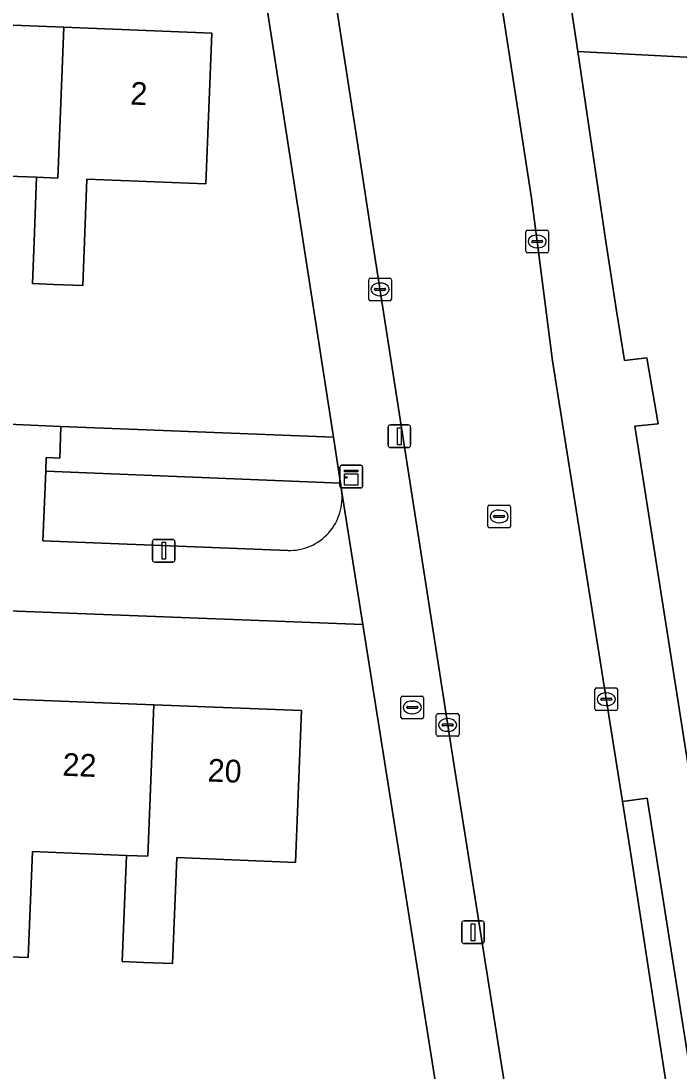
# Model space of a CAD drawing. Extents: x 160077 to 160948, y 386481 to 387498.
# Drawn here: x 160783.5 to 160812.49, y 386713.48 to 386759.71 of the extents above; entities that cross this region are included whole.
import ezdxf

# ---------------------------------------------------------------- set-up
doc = ezdxf.new("R2010")
doc.units = 0
for name, color, linetype in [('IMGEO_Brandkraan', 7, 'Continuous'), ('IMGEO_Erf', 7, 'Continuous'), ('IMGEO_Groenvoorziening', 7, 'Continuous'), ('IMGEO_Kast', 7, 'Continuous'), ('IMGEO_Kolk', 7, 'Continuous'), ('IMGEO_Lichtmast', 7, 'Continuous'), ('IMGEO_Pand', 7, 'Continuous'), ('IMGEO_Pand_nummerreeks', 7, 'Continuous'), ('IMGEO_Rijbaan_lokaal_open', 7, 'Continuous'), ('IMGEO_Rioolput', 7, 'Continuous'), ('IMGEO_Voetpad_open', 7, 'Continuous')]:
    doc.layers.add(name, color=color, linetype=linetype)

msp = doc.modelspace()

# ---------------------------------------------------------------- linework, layer by layer
at = {"layer": 'IMGEO_Brandkraan'}
for p, q in [((160800.311, 386729.989), (160801.163, 386729.989)), ((160800.236, 386729.063), (160800.236, 386729.915)), ((160800.495, 386729.483), (160800.495, 386729.495)), ((160800.538, 386729.532), (160800.936, 386729.532)), ((160800.724, 386729.769), (160800.749, 386729.769)), ((160800.979, 386729.495), (160800.979, 386729.483)), ((160801.237, 386729.915), (160801.237, 386729.063)), ((160800.933, 386729.446), (160800.535, 386729.446)), ((160800.747, 386729.209), (160800.722, 386729.209)), ((160801.163, 386728.989), (160800.311, 386728.989))]:
    msp.add_line(p, q, dxfattribs=at)
for points in [[(160800.311, 386729.989), (160801.163, 386729.989)], [(160800.236, 386729.063), (160800.236, 386729.915)], [(160801.237, 386729.915), (160801.237, 386729.063)], [(160801.163, 386728.989), (160800.311, 386728.989)]]:
    msp.add_lwpolyline(points, dxfattribs=at)
for centre, radius, start, end in [((160800.313, 386729.913), 0.0765, 91.552, 178.448), ((160800.313, 386729.913), 0.0765, 91.552, 178.448), ((160801.161, 386729.913), 0.0765, 1.552, 88.448), ((160801.161, 386729.913), 0.0765, 1.552, 88.448), ((160800.535, 386729.492), 0.0403, 85.8775, 175.7526), ((160800.532, 386729.482), 0.0366, 178.938, 274.7102), ((160800.936, 386729.489), 0.043, 264.8664, 352.4533), ((160800.94, 386729.494), 0.0386, 1.7309, 96.639), ((160800.313, 386729.065), 0.0765, 181.552, 268.448), ((160800.313, 386729.065), 0.0765, 181.552, 268.448), ((160801.161, 386729.065), 0.0765, 271.552, 358.448), ((160801.161, 386729.065), 0.0765, 271.552, 358.448)]:
    msp.add_arc(centre, radius, start, end, dxfattribs=at)
for centre, major_axis, ratio, start_param, end_param in [((160800.723, 386729.489), (-0.387, 0.002), 0.722429, 4.712389, 7.853982), ((160800.748, 386729.489), (-0.39, 0.002), 0.717154, 1.570796, 4.712389)]:
    msp.add_ellipse(centre, major_axis=major_axis, ratio=ratio, start_param=start_param, end_param=end_param, dxfattribs=at)
at = {"layer": 'IMGEO_Erf'}
msp.add_lwpolyline([(160795.925, 386750), (160793.898, 386763.085), (160730.396, 386765.489), (160732.727, 386750), (160733.656, 386743.829), (160744.313, 386743.428), (160746.852, 386743.334), (160757.001, 386742.953), (160759.549, 386742.857), (160769.844, 386742.471), (160772.371, 386742.376), (160782.604, 386741.967), (160785.258, 386741.861), (160797.26, 386741.38)], close=True, dxfattribs=at)
for points in [[(160779.022, 386759.684), (160785.389, 386759.431), (160791.909, 386759.172), (160791.645, 386752.535), (160786.4, 386752.743), (160786.296, 386750), (160786.222, 386748.061), (160784.939, 386748.11), (160784.005, 386748.145), (160784.075, 386750), (160784.181, 386752.827), (160780.018, 386752.985)], [(160801.998, 386711.476), (160798.554, 386733.131), (160734.945, 386735.584)], [(160782.99, 386729.857), (160789.346, 386729.605), (160795.857, 386729.346), (160795.591, 386722.666), (160790.364, 386722.88), (160790.172, 386718.21), (160788.895, 386718.263), (160787.961, 386718.301), (160788.152, 386722.969), (160784.002, 386723.139), (160783.809, 386718.469), (160782.54, 386718.521)]]:
    msp.add_lwpolyline(points, dxfattribs=at)
at = {"layer": 'IMGEO_Groenvoorziening'}
for points in [[(160823.518, 386765.871), (160820.354, 386766.006), (160815.188, 386766.228), (160811.851, 386766.514), (160806.916, 386765.741), (160808.027, 386758.373), (160823.217, 386757.574)], [(160797.572, 386739.366), (160797.26, 386741.38), (160785.258, 386741.861), (160785.202, 386740.461), (160784.609, 386740.485), (160784.585, 386739.886)]]:
    msp.add_lwpolyline(points, close=True, dxfattribs=at)
for points in [[(160830.716, 386750), (160831.303, 386765.056), (160831.285, 386765.525), (160826.272, 386765.754), (160823.518, 386765.871), (160823.217, 386757.574), (160808.027, 386758.373), (160809.27, 386750), (160809.736, 386746.952), (160810.081, 386744.76), (160811.075, 386744.88), (160811.572, 386741.979), (160810.536, 386741.865), (160812.902, 386726.822)], [(160797.621, 386739.052), (160797.572, 386739.366), (160784.585, 386739.886), (160784.463, 386736.822), (160795.254, 386736.397)]]:
    msp.add_lwpolyline(points, dxfattribs=at)
msp.add_arc((160795.324, 386738.717), 2.321, 268.2766, 8.2878, dxfattribs=at)
at = {"layer": 'IMGEO_Kast'}
for p, q in [((160797.625, 386740.149), (160798.466, 386740.149)), ((160798.466, 386740.149), (160797.625, 386740.149)), ((160797.55, 386739.224), (160797.55, 386740.065)), ((160797.55, 386740.065), (160797.55, 386739.224)), ((160798.55, 386740.074), (160798.55, 386739.233)), ((160798.55, 386739.233), (160798.55, 386740.074)), ((160798.475, 386739.149), (160797.634, 386739.149)), ((160797.634, 386739.149), (160798.475, 386739.149))]:
    msp.add_line(p, q, dxfattribs=at)
for points in [[(160797.745, 386739.939), (160798.345, 386739.939), (160798.345, 386739.854), (160797.745, 386739.854), (160797.745, 386739.939)], [(160797.745, 386739.764), (160798.345, 386739.764), (160798.345, 386739.275), (160797.745, 386739.275), (160797.745, 386739.764)]]:
    msp.add_lwpolyline(points, dxfattribs=at)
msp.add_circle((160797.829, 386739.613), 0.0377, dxfattribs=at)
for centre, start, end in [((160797.628, 386740.071), 92.4484, 184.2845), ((160797.628, 386740.071), 92.4484, 184.2845), ((160798.472, 386740.071), 2.4484, 94.2845), ((160798.472, 386740.071), 2.4484, 94.2845), ((160797.628, 386739.227), 182.4484, 274.2845), ((160797.628, 386739.227), 182.4484, 274.2845), ((160798.472, 386739.227), 272.4484, 4.2845), ((160798.472, 386739.227), 272.4484, 4.2845)]:
    msp.add_arc(centre, 0.0779, start, end, dxfattribs=at)
at = {"layer": 'IMGEO_Kolk'}
for p, q in [((160805.74, 386749.574), (160805.74, 386750.426)), ((160805.815, 386750.5), (160806.667, 386750.5)), ((160806.228, 386750.28), (160806.253, 386750.28)), ((160806.741, 386750.426), (160806.741, 386749.574)), ((160805.999, 386749.994), (160805.999, 386750.006)), ((160806.437, 386749.957), (160806.039, 386749.957)), ((160806.042, 386750.043), (160806.44, 386750.043)), ((160806.483, 386750.006), (160806.483, 386749.994)), ((160806.667, 386749.5), (160805.815, 386749.5)), ((160806.251, 386749.72), (160806.226, 386749.72)), ((160798.818, 386747.465), (160798.818, 386748.317)), ((160798.893, 386748.391), (160799.745, 386748.391)), ((160799.306, 386748.171), (160799.331, 386748.171)), ((160799.819, 386748.317), (160799.819, 386747.465)), ((160799.077, 386747.885), (160799.077, 386747.897)), ((160799.515, 386747.848), (160799.117, 386747.848)), ((160799.12, 386747.934), (160799.518, 386747.934)), ((160799.329, 386747.611), (160799.304, 386747.611)), ((160799.561, 386747.897), (160799.561, 386747.885)), ((160799.745, 386747.391), (160798.893, 386747.391)), ((160808.782, 386729.422), (160808.782, 386730.274)), ((160808.857, 386730.348), (160809.709, 386730.348)), ((160809.27, 386730.128), (160809.295, 386730.128)), ((160809.783, 386730.274), (160809.783, 386729.422)), ((160809.041, 386729.842), (160809.041, 386729.854)), ((160809.479, 386729.805), (160809.081, 386729.805)), ((160809.084, 386729.891), (160809.482, 386729.891)), ((160809.293, 386729.568), (160809.268, 386729.568)), ((160809.525, 386729.854), (160809.525, 386729.842)), ((160801.797, 386728.288), (160801.797, 386729.14)), ((160801.872, 386729.214), (160802.724, 386729.214)), ((160802.798, 386729.14), (160802.798, 386728.288)), ((160809.709, 386729.348), (160808.857, 386729.348)), ((160802.056, 386728.708), (160802.056, 386728.72)), ((160802.494, 386728.671), (160802.096, 386728.671)), ((160802.099, 386728.757), (160802.497, 386728.757)), ((160802.285, 386728.994), (160802.31, 386728.994)), ((160802.54, 386728.72), (160802.54, 386728.708)), ((160802.724, 386728.214), (160801.872, 386728.214)), ((160802.308, 386728.434), (160802.283, 386728.434))]:
    msp.add_line(p, q, dxfattribs=at)
for points in [[(160805.74, 386749.574), (160805.74, 386750.426)], [(160805.815, 386750.5), (160806.667, 386750.5)], [(160806.741, 386750.426), (160806.741, 386749.574)], [(160806.667, 386749.5), (160805.815, 386749.5)], [(160798.818, 386747.465), (160798.818, 386748.317)], [(160798.893, 386748.391), (160799.745, 386748.391)], [(160799.819, 386748.317), (160799.819, 386747.465)], [(160799.745, 386747.391), (160798.893, 386747.391)], [(160808.782, 386729.422), (160808.782, 386730.274)], [(160808.857, 386730.348), (160809.709, 386730.348)], [(160809.783, 386730.274), (160809.783, 386729.422)], [(160801.797, 386728.288), (160801.797, 386729.14)], [(160801.872, 386729.214), (160802.724, 386729.214)], [(160802.798, 386729.14), (160802.798, 386728.288)], [(160809.709, 386729.348), (160808.857, 386729.348)], [(160802.724, 386728.214), (160801.872, 386728.214)]]:
    msp.add_lwpolyline(points, dxfattribs=at)
for centre, radius, start, end in [((160805.817, 386750.424), 0.0765, 91.552, 178.448), ((160805.817, 386750.424), 0.0765, 91.552, 178.448), ((160806.665, 386750.424), 0.0765, 1.552, 88.448), ((160806.665, 386750.424), 0.0765, 1.552, 88.448), ((160806.039, 386750.003), 0.0403, 85.8775, 175.7526), ((160806.036, 386749.993), 0.0366, 178.938, 274.7102), ((160806.44, 386750), 0.043, 264.8664, 352.4533), ((160806.444, 386750.005), 0.0386, 1.7309, 96.639), ((160805.817, 386749.576), 0.0765, 181.552, 268.448), ((160805.817, 386749.576), 0.0765, 181.552, 268.448), ((160806.665, 386749.576), 0.0765, 271.552, 358.448), ((160806.665, 386749.576), 0.0765, 271.552, 358.448), ((160798.895, 386748.315), 0.0765, 91.552, 178.448), ((160798.895, 386748.315), 0.0765, 91.552, 178.448), ((160799.743, 386748.315), 0.0765, 1.552, 88.448), ((160799.743, 386748.315), 0.0765, 1.552, 88.448), ((160799.117, 386747.894), 0.0403, 85.8775, 175.7526), ((160799.114, 386747.884), 0.0366, 178.938, 274.7102), ((160799.518, 386747.891), 0.043, 264.8664, 352.4533), ((160799.522, 386747.896), 0.0386, 1.7309, 96.639), ((160798.895, 386747.467), 0.0765, 181.552, 268.448), ((160798.895, 386747.467), 0.0765, 181.552, 268.448), ((160799.743, 386747.467), 0.0765, 271.552, 358.448), ((160799.743, 386747.467), 0.0765, 271.552, 358.448), ((160808.859, 386730.272), 0.0765, 91.552, 178.448), ((160808.859, 386730.272), 0.0765, 91.552, 178.448), ((160809.707, 386730.272), 0.0765, 1.552, 88.448), ((160809.707, 386730.272), 0.0765, 1.552, 88.448), ((160809.081, 386729.851), 0.0403, 85.8775, 175.7526), ((160809.078, 386729.841), 0.0366, 178.938, 274.7102), ((160809.482, 386729.848), 0.043, 264.8664, 352.4533), ((160809.486, 386729.853), 0.0386, 1.7309, 96.639), ((160801.874, 386729.138), 0.0765, 91.552, 178.448), ((160801.874, 386729.138), 0.0765, 91.552, 178.448), ((160802.722, 386729.138), 0.0765, 1.552, 88.448), ((160802.722, 386729.138), 0.0765, 1.552, 88.448), ((160808.859, 386729.424), 0.0765, 181.552, 268.448), ((160808.859, 386729.424), 0.0765, 181.552, 268.448), ((160809.707, 386729.424), 0.0765, 271.552, 358.448), ((160809.707, 386729.424), 0.0765, 271.552, 358.448), ((160802.096, 386728.717), 0.0403, 85.8775, 175.7526), ((160802.093, 386728.707), 0.0366, 178.938, 274.7102), ((160802.497, 386728.714), 0.043, 264.8664, 352.4533), ((160802.501, 386728.719), 0.0386, 1.7309, 96.639), ((160801.874, 386728.29), 0.0765, 181.552, 268.448), ((160801.874, 386728.29), 0.0765, 181.552, 268.448), ((160802.722, 386728.29), 0.0765, 271.552, 358.448), ((160802.722, 386728.29), 0.0765, 271.552, 358.448)]:
    msp.add_arc(centre, radius, start, end, dxfattribs=at)
for centre, major_axis, ratio, start_param, end_param in [((160806.227, 386750), (-0.387, 0.002), 0.722429, 4.712389, 7.853982), ((160806.252, 386750), (-0.39, 0.002), 0.717154, 1.570796, 4.712389), ((160799.305, 386747.891), (-0.387, 0.002), 0.722429, 4.712389, 7.853982), ((160799.33, 386747.891), (-0.39, 0.002), 0.717154, 1.570796, 4.712389), ((160809.269, 386729.848), (-0.387, 0.002), 0.722429, 4.712389, 7.853982), ((160809.294, 386729.848), (-0.39, 0.002), 0.717154, 1.570796, 4.712389), ((160802.284, 386728.714), (-0.387, 0.002), 0.722429, 4.712389, 7.853982), ((160802.309, 386728.714), (-0.39, 0.002), 0.717154, 1.570796, 4.712389)]:
    msp.add_ellipse(centre, major_axis=major_axis, ratio=ratio, start_param=start_param, end_param=end_param, dxfattribs=at)
at = {"layer": 'IMGEO_Lichtmast'}
for p, q in [((160799.671, 386741.026), (160799.671, 386741.826)), ((160799.671, 386741.826), (160799.671, 386741.026)), ((160799.771, 386741.926), (160800.561, 386741.926)), ((160800.561, 386741.926), (160799.771, 386741.926)), ((160800.661, 386741.826), (160800.661, 386741.026)), ((160800.661, 386741.026), (160800.661, 386741.826)), ((160800.561, 386740.926), (160799.771, 386740.926)), ((160799.771, 386740.926), (160800.561, 386740.926)), ((160789.391, 386736.885), (160790.181, 386736.885)), ((160790.181, 386736.885), (160789.391, 386736.885)), ((160789.291, 386735.985), (160789.291, 386736.785)), ((160789.291, 386736.785), (160789.291, 386735.985)), ((160790.281, 386736.785), (160790.281, 386735.985)), ((160790.281, 386735.985), (160790.281, 386736.785)), ((160790.181, 386735.885), (160789.391, 386735.885)), ((160789.391, 386735.885), (160790.181, 386735.885)), ((160802.918, 386719.186), (160802.918, 386719.986)), ((160802.918, 386719.986), (160802.918, 386719.186)), ((160803.018, 386720.086), (160803.808, 386720.086)), ((160803.808, 386720.086), (160803.018, 386720.086)), ((160803.908, 386719.986), (160803.908, 386719.186)), ((160803.908, 386719.186), (160803.908, 386719.986)), ((160803.808, 386719.086), (160803.018, 386719.086)), ((160803.018, 386719.086), (160803.808, 386719.086))]:
    msp.add_line(p, q, dxfattribs=at)
for points in [[(160800.091, 386741.801), (160800.241, 386741.801), (160800.241, 386741.051), (160800.091, 386741.051), (160800.091, 386741.801)], [(160789.711, 386736.76), (160789.861, 386736.76), (160789.861, 386736.01), (160789.711, 386736.01), (160789.711, 386736.76)], [(160803.338, 386719.961), (160803.488, 386719.961), (160803.488, 386719.211), (160803.338, 386719.211), (160803.338, 386719.961)]]:
    msp.add_lwpolyline(points, dxfattribs=at)
for centre, start, end in [((160799.771, 386741.826), 90, 180), ((160799.771, 386741.826), 90, 180), ((160800.561, 386741.826), 0, 90), ((160800.561, 386741.826), 360, 90), ((160799.771, 386741.026), 180, 270), ((160799.771, 386741.026), 180, 270), ((160800.561, 386741.026), 270, 0), ((160800.561, 386741.026), 270, 0), ((160789.391, 386736.785), 90, 180), ((160789.391, 386736.785), 90, 180), ((160790.181, 386736.785), 0, 90), ((160790.181, 386736.785), 360, 90), ((160789.391, 386735.985), 180, 270), ((160789.391, 386735.985), 180, 270), ((160790.181, 386735.985), 270, 0), ((160790.181, 386735.985), 270, 0), ((160803.018, 386719.986), 90, 180), ((160803.018, 386719.986), 90, 180), ((160803.808, 386719.986), 0, 90), ((160803.808, 386719.986), 360, 90), ((160803.018, 386719.186), 180, 270), ((160803.018, 386719.186), 180, 270), ((160803.808, 386719.186), 270, 0), ((160803.808, 386719.186), 270, 0)]:
    msp.add_arc(centre, 0.1, start, end, dxfattribs=at)
at = {"layer": 'IMGEO_Pand'}
for points in [[(160785.389, 386759.431), (160779.022, 386759.684), (160778.757, 386753.031), (160777.8, 386753.068), (160777.683, 386750), (160777.667, 386749.576), (160777.622, 386748.385), (160778.571, 386748.349), (160779.839, 386748.3), (160779.904, 386750), (160780.018, 386752.985), (160784.181, 386752.827), (160785.125, 386752.79)], [(160784.075, 386750), (160784.005, 386748.145), (160784.939, 386748.11), (160786.222, 386748.061), (160786.296, 386750), (160786.4, 386752.743), (160791.645, 386752.535), (160791.909, 386759.172), (160785.389, 386759.431), (160785.125, 386752.79), (160784.181, 386752.827)], [(160782.54, 386718.521), (160783.809, 386718.469), (160784.002, 386723.139), (160788.152, 386722.969), (160789.081, 386722.933), (160789.346, 386729.605), (160782.99, 386729.857), (160782.725, 386723.192), (160781.79, 386723.229), (160781.598, 386718.56)], [(160788.895, 386718.263), (160790.172, 386718.21), (160790.364, 386722.88), (160795.591, 386722.666), (160795.857, 386729.346), (160789.346, 386729.605), (160789.081, 386722.933), (160788.152, 386722.969), (160787.961, 386718.301)]]:
    msp.add_lwpolyline(points, close=True, dxfattribs=at)
at = {"layer": 'IMGEO_Rijbaan_lokaal_open'}
msp.add_lwpolyline([(160813.836, 386700.495), (160810.411, 386722.747), (160809.998, 386725.345), (160806.912, 386744.746), (160806.241, 386750), (160805.996, 386751.914), (160804.256, 386763.136), (160803.036, 386770.539), (160800.264, 386788.501), (160800.062, 386789.668), (160793.031, 386788.583), (160794.727, 386777.599), (160795.33, 386773.695), (160798.275, 386754.619), (160798.992, 386750), (160802.535, 386727.194), (160807.755, 386694.276), (160809.921, 386680.44), (160810.008, 386680.46), (160812.135, 386661.504), (160812.011, 386661.39), (160810.958, 386636.637), (160810.118, 386615.402)], dxfattribs=at)
at = {"layer": 'IMGEO_Rioolput'}
for p, q in [((160804.064, 386737.468), (160804.064, 386738.32)), ((160804.139, 386738.394), (160804.991, 386738.394)), ((160805.065, 386738.32), (160805.065, 386737.468)), ((160804.323, 386737.888), (160804.323, 386737.9)), ((160804.761, 386737.851), (160804.363, 386737.851)), ((160804.366, 386737.937), (160804.764, 386737.937)), ((160804.552, 386738.174), (160804.577, 386738.174)), ((160804.807, 386737.9), (160804.807, 386737.888)), ((160804.991, 386737.394), (160804.139, 386737.394)), ((160804.575, 386737.614), (160804.55, 386737.614))]:
    msp.add_line(p, q, dxfattribs=at)
for points in [[(160804.064, 386737.468), (160804.064, 386738.32)], [(160804.139, 386738.394), (160804.991, 386738.394)], [(160805.065, 386738.32), (160805.065, 386737.468)], [(160804.991, 386737.394), (160804.139, 386737.394)]]:
    msp.add_lwpolyline(points, dxfattribs=at)
for centre, radius, start, end in [((160804.141, 386738.318), 0.0765, 91.552, 178.448), ((160804.141, 386738.318), 0.0765, 91.552, 178.448), ((160804.989, 386738.318), 0.0765, 1.552, 88.448), ((160804.989, 386738.318), 0.0765, 1.552, 88.448), ((160804.363, 386737.897), 0.0403, 85.8775, 175.7526), ((160804.36, 386737.887), 0.0366, 178.938, 274.7102), ((160804.764, 386737.894), 0.043, 264.8664, 352.4533), ((160804.768, 386737.899), 0.0386, 1.7309, 96.639), ((160804.141, 386737.47), 0.0765, 181.552, 268.448), ((160804.141, 386737.47), 0.0765, 181.552, 268.448), ((160804.989, 386737.47), 0.0765, 271.552, 358.448), ((160804.989, 386737.47), 0.0765, 271.552, 358.448)]:
    msp.add_arc(centre, radius, start, end, dxfattribs=at)
for centre, major_axis, ratio, start_param, end_param in [((160804.551, 386737.894), (-0.387, 0.002), 0.722429, 4.712389, 7.853982), ((160804.576, 386737.894), (-0.39, 0.002), 0.717154, 1.570796, 4.712389)]:
    msp.add_ellipse(centre, major_axis=major_axis, ratio=ratio, start_param=start_param, end_param=end_param, dxfattribs=at)
at = {"layer": 'IMGEO_Voetpad_open'}
for points in [[(160812.902, 386726.822), (160810.536, 386741.865), (160811.572, 386741.979), (160811.075, 386744.88), (160810.081, 386744.76), (160809.736, 386746.952), (160809.27, 386750), (160808.027, 386758.373), (160806.916, 386765.741), (160802.867, 386790.622), (160802.632, 386791.694), (160802.511, 386791.738), (160801.74, 386796.471)], [(160729.654, 386770.62), (160729.514, 386771.537), (160729.208, 386773.55), (160726.113, 386793.887), (160723.157, 386793.323), (160725.146, 386779.949), (160726.211, 386772.948), (160727.336, 386765.387), (160727.652, 386763.274), (160727.675, 386763.262), (160728.639, 386757.007), (160729.721, 386750), (160729.967, 386748.41), (160730.959, 386741.615), (160731.883, 386735.296), (160734.945, 386735.584), (160798.554, 386733.131), (160797.621, 386739.052)], [(160799.617, 386791.295), (160800.062, 386789.668), (160800.555, 386789.754), (160804.746, 386763.241), (160804.256, 386763.136), (160805.996, 386751.914), (160806.241, 386750), (160806.912, 386744.746), (160809.998, 386725.345), (160811.089, 386725.486), (160816.298, 386692.41)], [(160802.535, 386727.194), (160798.992, 386750), (160798.275, 386754.619), (160795.33, 386773.695), (160794.836, 386773.62), (160794.233, 386777.524), (160794.727, 386777.599), (160793.031, 386788.583), (160792.719, 386790.606)], [(160793.898, 386763.085), (160795.925, 386750), (160797.26, 386741.38), (160797.572, 386739.366), (160797.621, 386739.052), (160798.554, 386733.131), (160801.998, 386711.476)], [(160795.254, 386736.397), (160784.463, 386736.822), (160784.585, 386739.886), (160784.609, 386740.485), (160785.202, 386740.461), (160785.258, 386741.861), (160782.604, 386741.967)], [(160809.921, 386680.44), (160807.755, 386694.276), (160802.535, 386727.194)]]:
    msp.add_lwpolyline(points, dxfattribs=at)
msp.add_lwpolyline([(160815.305, 386691.678), (160815.299, 386691.743), (160815.299, 386691.797), (160815.303, 386691.851), (160815.313, 386691.904), (160815.327, 386691.956), (160815.346, 386692.006), (160815.37, 386692.055), (160815.397, 386692.101), (160815.429, 386692.145), (160815.464, 386692.185), (160815.503, 386692.223), (160815.545, 386692.257), (160815.59, 386692.286), (160815.637, 386692.312), (160815.687, 386692.333), (160815.738, 386692.35), (160815.791, 386692.363), (160815.844, 386692.37), (160816.298, 386692.41), (160811.089, 386725.486), (160809.998, 386725.345), (160810.411, 386722.747), (160813.836, 386700.495)], close=True, dxfattribs=at)
msp.add_arc((160795.324, 386738.717), 2.321, 268.2766, 8.2878, dxfattribs=at)

# ---------------------------------------------------------------- texts
at = {"layer": 'IMGEO_Pand_nummerreeks'}
for s, rotation, p in [('2', 357.7255, (160788.302, 386756.032)), ('22', 357.7236, (160785.314, 386726.482)), ('20', 357.7236, (160791.71, 386726.228))]:
    msp.add_text(s, height=1, rotation=rotation, dxfattribs=at).set_placement(p)

doc.saveas('drawing.dxf')
